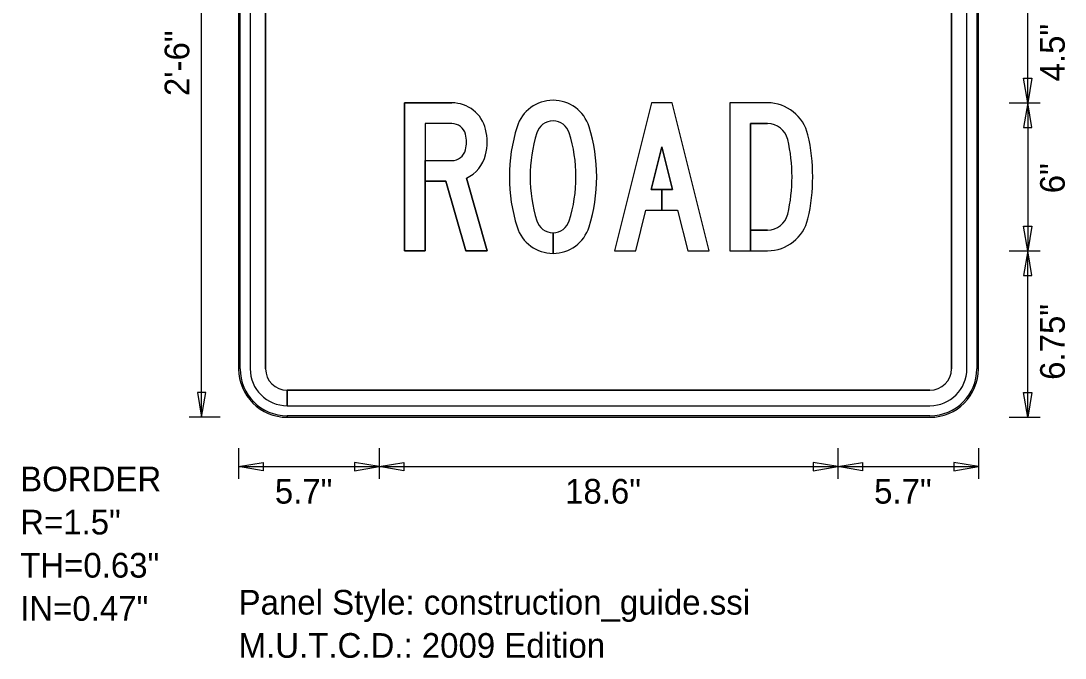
# Model space of a CAD drawing. Extents: x 1775472.9 to 1775494.7, y 1032415.7 to 1032420.8.
# Drawn here: x 1775472.857 to 1775477.092, y 1032415.654 to 1032418.237 of the extents above; entities that cross this region are included whole.
import ezdxf

# ---------------------------------------------------------------- set-up
doc = ezdxf.new("R2010")
doc.units = 0
for name, color, linetype in [('Default', 7, 'Continuous'), ('GSBWFILL', 7, 'Continuous'), ('GSCOLORFILL', 7, 'Continuous'), ('GSOUTLINE', 7, 'Continuous')]:
    doc.layers.add(name, color=color, linetype=linetype)

msp = doc.modelspace()

# ---------------------------------------------------------------- linework, layer by layer
at = {"layer": 'Default'}
for p, q in [((1775473.5901, 1032416.6302), (1775473.5901, 1032419.6302)), ((1775476.9401, 1032417.9052), (1775476.9401, 1032418.3552)), ((1775476.8651, 1032417.9052), (1775476.9901, 1032417.9052)), ((1775476.8651, 1032417.9052), (1775476.9901, 1032417.9052)), ((1775476.9401, 1032417.9052), (1775476.9401, 1032417.3052)), ((1775476.8651, 1032417.3052), (1775476.9901, 1032417.3052)), ((1775476.8651, 1032417.3052), (1775476.9901, 1032417.3052)), ((1775476.9401, 1032416.6302), (1775476.9401, 1032417.3052)), ((1775473.6651, 1032416.6302), (1775473.5401, 1032416.6302)), ((1775473.6651, 1032416.6302), (1775473.6651, 1032416.6302)), ((1775476.8651, 1032416.6302), (1775476.9901, 1032416.6302)), ((1775476.8651, 1032416.6302), (1775476.8651, 1032416.6302)), ((1775473.7401, 1032416.5052), (1775473.7401, 1032416.3802)), ((1775473.7401, 1032416.5052), (1775473.7401, 1032416.3802)), ((1775474.3101, 1032416.5052), (1775474.3101, 1032416.3802)), ((1775474.3101, 1032416.5052), (1775474.3101, 1032416.3802)), ((1775476.1701, 1032416.5052), (1775476.1701, 1032416.3802)), ((1775476.1701, 1032416.5052), (1775476.1701, 1032416.3802)), ((1775476.7401, 1032416.5052), (1775476.7401, 1032416.3802)), ((1775476.7401, 1032416.5052), (1775476.7401, 1032416.3802)), ((1775473.7401, 1032416.4302), (1775474.3101, 1032416.4302)), ((1775474.3101, 1032416.4302), (1775476.1701, 1032416.4302)), ((1775476.1701, 1032416.4302), (1775476.7401, 1032416.4302))]:
    msp.add_line(p, q, dxfattribs=at)
for points in [[(1775476.9401, 1032417.9052), (1775476.9234, 1032418.0052), (1775476.9568, 1032418.0052)], [(1775476.9401, 1032417.9052), (1775476.9234, 1032417.8052), (1775476.9568, 1032417.8052)], [(1775476.9401, 1032417.3052), (1775476.9234, 1032417.4052), (1775476.9568, 1032417.4052)], [(1775476.9401, 1032417.3052), (1775476.9234, 1032417.2052), (1775476.9568, 1032417.2052)], [(1775473.5901, 1032416.6302), (1775473.6068, 1032416.7302), (1775473.5734, 1032416.7302)], [(1775476.9401, 1032416.6302), (1775476.9234, 1032416.7302), (1775476.9568, 1032416.7302)], [(1775473.7401, 1032416.4302), (1775473.8401, 1032416.4469), (1775473.8401, 1032416.4135)], [(1775474.3101, 1032416.4302), (1775474.2101, 1032416.4469), (1775474.2101, 1032416.4135)], [(1775474.3101, 1032416.4302), (1775474.4101, 1032416.4469), (1775474.4101, 1032416.4135)], [(1775476.1701, 1032416.4302), (1775476.0701, 1032416.4469), (1775476.0701, 1032416.4135)], [(1775476.1701, 1032416.4302), (1775476.2701, 1032416.4469), (1775476.2701, 1032416.4135)], [(1775476.7401, 1032416.4302), (1775476.6401, 1032416.4469), (1775476.6401, 1032416.4135)]]:
    msp.add_lwpolyline(points, close=True, dxfattribs=at)
at = {"layer": 'GSBWFILL'}
for p, q in [((1775473.7401, 1032419.4333), (1775473.7401, 1032416.8271)), ((1775473.787, 1032419.4333), (1775473.787, 1032416.8271)), ((1775473.8495, 1032416.8271), (1775473.8495, 1032419.4333)), ((1775476.6307, 1032419.4333), (1775476.6307, 1032416.8271)), ((1775476.6932, 1032416.8271), (1775476.6932, 1032419.4333)), ((1775476.7401, 1032416.8271), (1775476.7401, 1032419.4333)), ((1775474.6049, 1032417.6712), (1775474.6049, 1032417.6712)), ((1775475.8849, 1032417.3892), (1775475.8161, 1032417.3892)), ((1775475.0151, 1032417.3787), (1775475.0151, 1032417.2947)), ((1775475.0151, 1032417.2947), (1775475.0151, 1032417.3787)), ((1775473.937, 1032416.6771), (1775473.937, 1032416.7396)), ((1775476.5432, 1032416.7396), (1775473.9376, 1032416.7396)), ((1775473.9376, 1032416.7396), (1775473.9376, 1032416.6771)), ((1775473.9376, 1032416.6771), (1775476.5432, 1032416.6771)), ((1775473.937, 1032416.6302), (1775476.5432, 1032416.6302))]:
    msp.add_line(p, q, dxfattribs=at)
for points in [[(1775474.6049, 1032417.8212), (1775474.4961, 1032417.8212), (1775474.4961, 1032417.3052), (1775474.4121, 1032417.3052), (1775474.4121, 1032417.9052), (1775474.6049, 1032417.9052)], [(1775475.8849, 1032417.9052), (1775475.7321, 1032417.9052), (1775475.7321, 1032417.3052), (1775475.8161, 1032417.3052), (1775475.8161, 1032417.8212), (1775475.8849, 1032417.8212)], [(1775474.6641, 1032417.6002), (1775474.7481, 1032417.3052), (1775474.6608, 1032417.3052), (1775474.5805, 1032417.5872), (1775474.4961, 1032417.5872), (1775474.4961, 1032417.6712), (1775474.6049, 1032417.6712)], [(1775475.8161, 1032417.3892), (1775475.8161, 1032417.3052), (1775475.8849, 1032417.3052)]]:
    msp.add_lwpolyline(points, dxfattribs=at)
msp.add_lwpolyline([(1775475.4561, 1032417.5542), (1775475.4129, 1032417.5542), (1775475.4561, 1032417.7269), (1775475.4993, 1032417.5542), (1775475.4561, 1032417.5542), (1775475.4561, 1032417.4702), (1775475.5203, 1032417.4702), (1775475.5615, 1032417.3052), (1775475.6481, 1032417.3052), (1775475.4981, 1032417.9052), (1775475.4141, 1032417.9052), (1775475.2641, 1032417.3052), (1775475.3507, 1032417.3052), (1775475.3919, 1032417.4702), (1775475.4561, 1032417.4702)], close=True, dxfattribs=at)
for centre, radius, start, end in [((1775474.6049, 1032417.7642), 0.141, 13.8865, 90), ((1775475.0151, 1032417.7627), 0.153, 17.3283, 162.6717), ((1775475.8849, 1032417.7372), 0.168, 13.109, 90), ((1775474.6049, 1032417.7642), 0.057, 13.8865, 90), ((1775475.5199, 1032417.6052), 0.6818, 162.6717, 197.3283), ((1775475.0151, 1032417.7627), 0.069, 17.3283, 162.6717), ((1775474.5103, 1032417.6052), 0.6818, 342.6717, 17.3283), ((1775475.8849, 1032417.7372), 0.084, 13.109, 90), ((1775474.5321, 1032417.7462), 0.132, 346.1135, 13.8865), ((1775474.5321, 1032417.7462), 0.216, 346.1135, 13.8865), ((1775475.5199, 1032417.6052), 0.5978, 162.6717, 197.3283), ((1775474.5103, 1032417.6052), 0.5978, 342.6717, 17.3283), ((1775475.3181, 1032417.6052), 0.75, 346.891, 13.109), ((1775475.3181, 1032417.6052), 0.666, 346.891, 13.109), ((1775474.6049, 1032417.7282), 0.057, 270, 346.1135), ((1775474.6049, 1032417.7282), 0.141, 294.8221, 346.1135), ((1775475.0151, 1032417.4477), 0.069, 197.3283, 270), ((1775475.0151, 1032417.4477), 0.069, 270.0249, 342.6717), ((1775475.8849, 1032417.4732), 0.084, 270, 346.891), ((1775475.8849, 1032417.4732), 0.168, 270, 346.891), ((1775475.0151, 1032417.4477), 0.153, 197.3283, 270), ((1775475.0151, 1032417.4477), 0.153, 270.0112, 342.6717), ((1775473.937, 1032416.8271), 0.1969, 180, 270), ((1775473.937, 1032416.8271), 0.15, 180, 270), ((1775473.937, 1032416.8271), 0.0875, 180, 270), ((1775476.5432, 1032416.8271), 0.15, 270, 0), ((1775476.5432, 1032416.8271), 0.0875, 270, 0), ((1775476.5432, 1032416.8271), 0.1969, 270, 0)]:
    msp.add_arc(centre, radius, start, end, dxfattribs=at)
at = {"layer": 'GSCOLORFILL'}
for p, q in [((1775473.7401, 1032419.4333), (1775473.7401, 1032416.8271)), ((1775473.7401, 1032419.4333), (1775473.7401, 1032416.8271)), ((1775473.7463, 1032416.8271), (1775473.7463, 1032419.4333)), ((1775473.787, 1032419.4333), (1775473.787, 1032416.8271)), ((1775473.8495, 1032416.8271), (1775473.8495, 1032419.4333)), ((1775476.6307, 1032419.4333), (1775476.6307, 1032416.8271)), ((1775476.6932, 1032416.8271), (1775476.6932, 1032419.4333)), ((1775476.7338, 1032419.4333), (1775476.7338, 1032416.8271)), ((1775476.7401, 1032416.8271), (1775476.7401, 1032419.4333)), ((1775476.7401, 1032416.8271), (1775476.7401, 1032419.4333)), ((1775474.6049, 1032417.6712), (1775474.6049, 1032417.6712)), ((1775475.8849, 1032417.3892), (1775475.8161, 1032417.3892)), ((1775475.0151, 1032417.3787), (1775475.0151, 1032417.2947)), ((1775475.0151, 1032417.2947), (1775475.0151, 1032417.3787)), ((1775473.937, 1032416.6771), (1775473.937, 1032416.7396)), ((1775476.5432, 1032416.7396), (1775473.9376, 1032416.7396)), ((1775473.9376, 1032416.7396), (1775473.9376, 1032416.6771)), ((1775473.9376, 1032416.6771), (1775476.5432, 1032416.6771)), ((1775473.937, 1032416.6302), (1775473.937, 1032416.6364)), ((1775476.5432, 1032416.6364), (1775473.937, 1032416.6364)), ((1775473.937, 1032416.6364), (1775473.937, 1032416.6302)), ((1775473.937, 1032416.6302), (1775476.5432, 1032416.6302)), ((1775473.937, 1032416.6302), (1775476.5432, 1032416.6302))]:
    msp.add_line(p, q, dxfattribs=at)
for points in [[(1775474.6049, 1032417.8212), (1775474.4961, 1032417.8212), (1775474.4961, 1032417.3052), (1775474.4121, 1032417.3052), (1775474.4121, 1032417.9052), (1775474.6049, 1032417.9052)], [(1775475.8849, 1032417.9052), (1775475.7321, 1032417.9052), (1775475.7321, 1032417.3052), (1775475.8161, 1032417.3052), (1775475.8161, 1032417.8212), (1775475.8849, 1032417.8212)], [(1775474.6641, 1032417.6002), (1775474.7481, 1032417.3052), (1775474.6608, 1032417.3052), (1775474.5805, 1032417.5872), (1775474.4961, 1032417.5872), (1775474.4961, 1032417.6712), (1775474.6049, 1032417.6712)], [(1775475.8161, 1032417.3892), (1775475.8161, 1032417.3052), (1775475.8849, 1032417.3052)]]:
    msp.add_lwpolyline(points, dxfattribs=at)
msp.add_lwpolyline([(1775475.4561, 1032417.5542), (1775475.4129, 1032417.5542), (1775475.4561, 1032417.7269), (1775475.4993, 1032417.5542), (1775475.4561, 1032417.5542), (1775475.4561, 1032417.4702), (1775475.5203, 1032417.4702), (1775475.5615, 1032417.3052), (1775475.6481, 1032417.3052), (1775475.4981, 1032417.9052), (1775475.4141, 1032417.9052), (1775475.2641, 1032417.3052), (1775475.3507, 1032417.3052), (1775475.3919, 1032417.4702), (1775475.4561, 1032417.4702)], close=True, dxfattribs=at)
for centre, radius, start, end in [((1775474.6049, 1032417.7642), 0.141, 13.8865, 90), ((1775475.0151, 1032417.7627), 0.153, 17.3283, 162.6717), ((1775475.8849, 1032417.7372), 0.168, 13.109, 90), ((1775474.6049, 1032417.7642), 0.057, 13.8865, 90), ((1775475.5199, 1032417.6052), 0.6818, 162.6717, 197.3283), ((1775475.0151, 1032417.7627), 0.069, 17.3283, 162.6717), ((1775474.5103, 1032417.6052), 0.6818, 342.6717, 17.3283), ((1775475.8849, 1032417.7372), 0.084, 13.109, 90), ((1775474.5321, 1032417.7462), 0.132, 346.1135, 13.8865), ((1775474.5321, 1032417.7462), 0.216, 346.1135, 13.8865), ((1775475.5199, 1032417.6052), 0.5978, 162.6717, 197.3283), ((1775474.5103, 1032417.6052), 0.5978, 342.6717, 17.3283), ((1775475.3181, 1032417.6052), 0.75, 346.891, 13.109), ((1775475.3181, 1032417.6052), 0.666, 346.891, 13.109), ((1775474.6049, 1032417.7282), 0.057, 270, 346.1135), ((1775474.6049, 1032417.7282), 0.141, 294.8221, 346.1135), ((1775475.0151, 1032417.4477), 0.069, 197.3283, 270), ((1775475.0151, 1032417.4477), 0.069, 270.0249, 342.6717), ((1775475.8849, 1032417.4732), 0.084, 270, 346.891), ((1775475.8849, 1032417.4732), 0.168, 270, 346.891), ((1775475.0151, 1032417.4477), 0.153, 197.3283, 270), ((1775475.0151, 1032417.4477), 0.153, 270.0112, 342.6717), ((1775473.937, 1032416.8271), 0.1969, 180, 270), ((1775473.937, 1032416.8271), 0.1969, 180, 270), ((1775473.937, 1032416.8271), 0.1906, 180, 270), ((1775473.937, 1032416.8271), 0.15, 180, 270), ((1775473.937, 1032416.8271), 0.0875, 180, 270), ((1775476.5432, 1032416.8271), 0.1969, 270, 0), ((1775476.5432, 1032416.8271), 0.15, 270, 0), ((1775476.5432, 1032416.8271), 0.0875, 270, 0), ((1775476.5432, 1032416.8271), 0.1969, 270, 0), ((1775476.5432, 1032416.8271), 0.1906, 270, 0)]:
    msp.add_arc(centre, radius, start, end, dxfattribs=at)
at = {"layer": 'GSOUTLINE'}
for p, q in [((1775473.7401, 1032419.4333), (1775473.7401, 1032416.8271)), ((1775473.787, 1032419.4333), (1775473.787, 1032416.8271)), ((1775473.8495, 1032419.4333), (1775473.8495, 1032416.8271)), ((1775476.6307, 1032416.8271), (1775476.6307, 1032419.4333)), ((1775476.6932, 1032416.8271), (1775476.6932, 1032419.4333)), ((1775476.7401, 1032416.8271), (1775476.7401, 1032419.4333)), ((1775474.6049, 1032417.9052), (1775474.4121, 1032417.9052)), ((1775474.6049, 1032417.8212), (1775474.6049, 1032417.8212)), ((1775475.8161, 1032417.3892), (1775475.8849, 1032417.3892)), ((1775475.8849, 1032417.3052), (1775475.8849, 1032417.3052)), ((1775473.937, 1032416.7396), (1775476.5432, 1032416.7396)), ((1775473.937, 1032416.6771), (1775476.5432, 1032416.6771)), ((1775473.937, 1032416.6302), (1775476.5432, 1032416.6302))]:
    msp.add_line(p, q, dxfattribs=at)
for points in [[(1775474.4121, 1032417.9052), (1775474.4121, 1032417.3052), (1775474.4961, 1032417.3052), (1775474.4961, 1032417.5872), (1775474.5805, 1032417.5872), (1775474.6608, 1032417.3052), (1775474.7481, 1032417.3052), (1775474.6641, 1032417.6002)], [(1775475.8849, 1032417.9052), (1775475.7321, 1032417.9052), (1775475.7321, 1032417.3052), (1775475.8849, 1032417.3052)], [(1775474.6049, 1032417.8212), (1775474.4961, 1032417.8212), (1775474.4961, 1032417.6712), (1775474.6049, 1032417.6712)], [(1775475.8849, 1032417.8212), (1775475.8161, 1032417.8212), (1775475.8161, 1032417.3892)]]:
    msp.add_lwpolyline(points, dxfattribs=at)
for points in [[(1775475.3919, 1032417.4702), (1775475.5203, 1032417.4702), (1775475.5615, 1032417.3052), (1775475.6481, 1032417.3052), (1775475.4981, 1032417.9052), (1775475.4141, 1032417.9052), (1775475.2641, 1032417.3052), (1775475.3507, 1032417.3052)], [(1775475.4993, 1032417.5542), (1775475.4561, 1032417.7269), (1775475.4129, 1032417.5542)]]:
    msp.add_lwpolyline(points, close=True, dxfattribs=at)
for centre, radius, start, end in [((1775474.6049, 1032417.7642), 0.141, 13.8865, 90), ((1775475.0151, 1032417.7627), 0.153, 17.3283, 162.6717), ((1775475.8849, 1032417.7372), 0.168, 13.109, 90), ((1775474.6049, 1032417.7642), 0.057, 13.8865, 90), ((1775475.5199, 1032417.6052), 0.6818, 162.6717, 197.3283), ((1775475.0151, 1032417.7627), 0.069, 17.3283, 162.6717), ((1775474.5103, 1032417.6052), 0.6818, 342.6717, 17.3283), ((1775475.8849, 1032417.7372), 0.084, 13.109, 90), ((1775474.5321, 1032417.7462), 0.132, 346.1135, 13.8865), ((1775474.5321, 1032417.7462), 0.216, 346.1135, 13.8865), ((1775475.5199, 1032417.6052), 0.5978, 162.6717, 197.3283), ((1775474.5103, 1032417.6052), 0.5978, 342.6717, 17.3283), ((1775475.3181, 1032417.6052), 0.75, 346.891, 13.109), ((1775475.3181, 1032417.6052), 0.666, 346.891, 13.109), ((1775474.6049, 1032417.7282), 0.057, 270, 346.1135), ((1775474.6049, 1032417.7282), 0.141, 294.8221, 346.1135), ((1775475.0151, 1032417.4477), 0.069, 197.3283, 342.6717), ((1775475.8849, 1032417.4732), 0.084, 270, 346.891), ((1775475.8849, 1032417.4732), 0.168, 270, 346.891), ((1775475.0151, 1032417.4477), 0.153, 197.3283, 342.6717), ((1775473.937, 1032416.8271), 0.1969, 180, 270), ((1775473.937, 1032416.8271), 0.15, 180, 270), ((1775473.937, 1032416.8271), 0.0875, 180, 270), ((1775476.5432, 1032416.8271), 0.15, 270, 0), ((1775476.5432, 1032416.8271), 0.0875, 270, 0), ((1775476.5432, 1032416.8271), 0.1969, 270, 0)]:
    msp.add_arc(centre, radius, start, end, dxfattribs=at)

# ---------------------------------------------------------------- texts
at = {"layer": 'Default'}
for s, p in [('2\'-6"', (1775473.5401, 1032417.9325)), ('4.5"', (1775477.0901, 1032417.9921)), ('6"', (1775477.0901, 1032417.5385)), ('6.75"', (1775477.0901, 1032416.7819))]:
    msp.add_text(s, height=0.1, rotation=90, dxfattribs=at).set_placement(p)
for s, p in [('BORDER', (1775472.8542, 1032416.3302)), ('5.7"', (1775473.887, 1032416.2802)), ('18.6"', (1775475.0639, 1032416.2802)), ('5.7"', (1775476.317, 1032416.2802)), ('R=1.5"', (1775472.8542, 1032416.1552)), ('TH=0.63"', (1775472.8542, 1032415.9802)), ('IN=0.47"', (1775472.8542, 1032415.8052)), ('Panel Style: construction_guide.ssi', (1775473.7401, 1032415.8302)), ('M.U.T.C.D.: 2009 Edition', (1775473.7401, 1032415.6552))]:
    msp.add_text(s, height=0.1, dxfattribs=at).set_placement(p)

doc.saveas('drawing.dxf')
